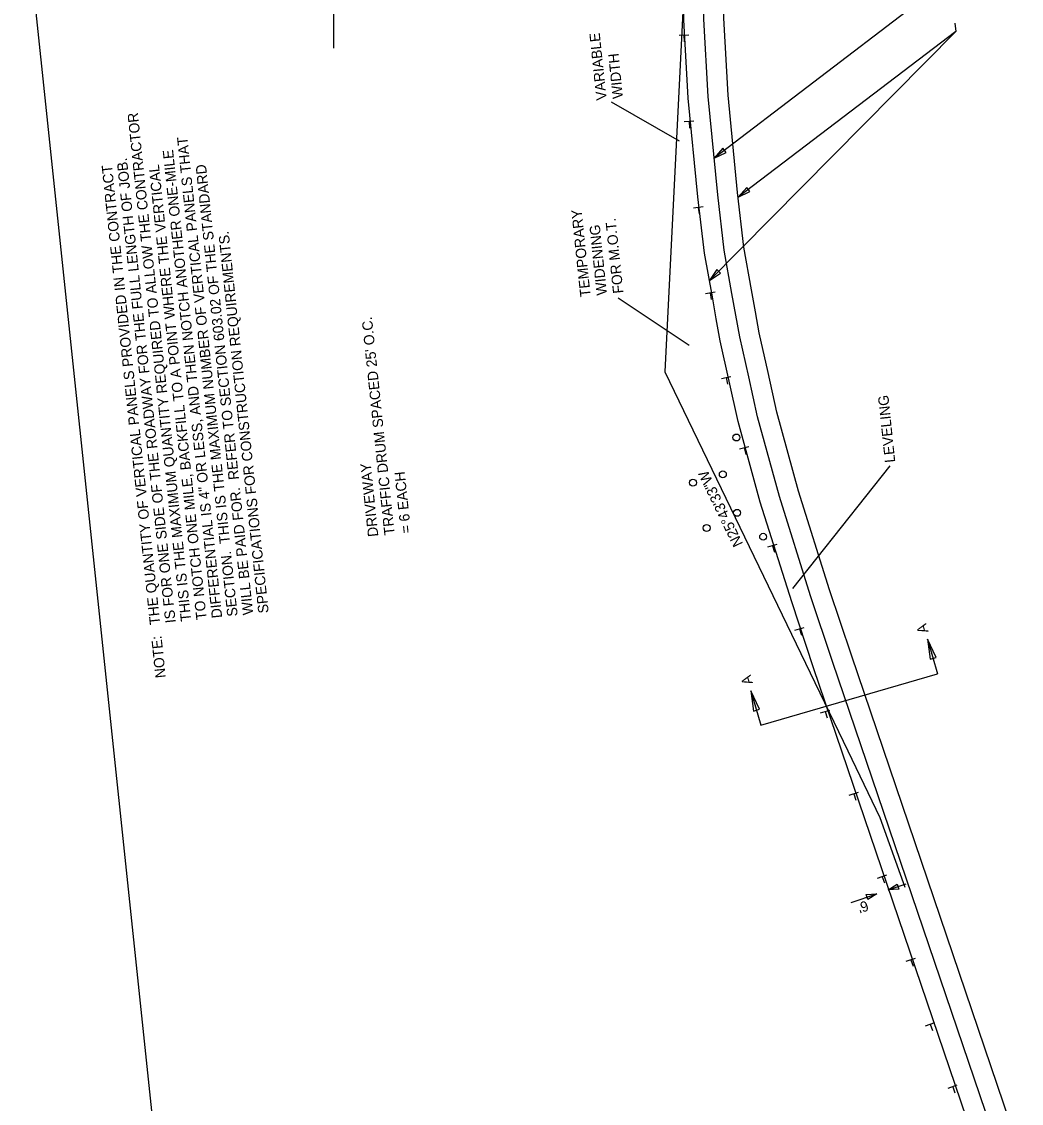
# Model space of a CAD drawing. Extents: x 633427 to 634998, y 288285 to 294065.
# Drawn here: x 633842 to 634420, y 288854 to 289479 of the extents above; entities that cross this region are included whole.
import ezdxf

# ---------------------------------------------------------------- set-up
doc = ezdxf.new("R2010")
doc.units = 0
for name, color, linetype in [('59', 7, 'Continuous'), ('Default', 7, 'Continuous'), ('R_50 Horz Alg Ticks', 7, 'Continuous'), ('R_Exist Surface', 7, 'Continuous'), ('R_Vert Alg Annot', 7, 'Continuous'), ('S_BASELINE', 7, 'Continuous'), ('S_GATE', 7, 'Continuous'), ('S_GUARDRAIL', 7, 'Continuous'), ('S_PRIMARY_CTL', 7, 'Continuous'), ('S_SECONDARY_CTL', 7, 'Continuous'), ('S_WATER_UTILITIES', 7, 'Continuous')]:
    doc.layers.add(name, color=color, linetype=linetype)

msp = doc.modelspace()

# ---------------------------------------------------------------- linework, layer by layer
at = {"layer": '59'}
for p, q in [((634221.97, 289471.22), (634227.59, 289471.46)), ((634224.77, 289471.26), (634224.94, 289467.42)), ((634224.92, 289421.3), (634230.53, 289421.68)), ((634227.72, 289421.41), (634227.97, 289417.57)), ((634230.29, 289371.5), (634235.88, 289372.13)), ((634233.08, 289371.73), (634233.51, 289367.92)), ((634237.22, 289321.97), (634242.77, 289322.85)), ((634240, 289322.33), (634240.59, 289318.53)), ((634246.43, 289272.93), (634251.94, 289274.09)), ((634249.19, 289273.43), (634249.98, 289269.67)), ((634256.89, 289232.14), (634262.34, 289233.54)), ((634259.62, 289232.76), (634260.57, 289229.04)), ((634273.27, 289175.53), (634278.66, 289177.15)), ((634275.97, 289176.26), (634277.08, 289172.58)), ((634288.91, 289127.43), (634294.29, 289129.05)), ((634291.61, 289128.16), (634292.72, 289124.48)), ((634303.68, 289079.68), (634309.07, 289081.3)), ((634306.39, 289080.41), (634307.5, 289076.73)), ((634320.18, 289032.17), (634325.57, 289033.8)), ((634322.88, 289032.9), (634323.99, 289029.23)), ((634336.62, 288984.22), (634341.94, 288986.04)), ((634339.29, 288985.05), (634340.53, 288981.42)), ((634353.16, 288936.15), (634358.49, 288937.96)), ((634355.84, 288936.97), (634357.08, 288933.34)), ((634364.36, 288898.95), (634369.68, 288900.77)), ((634367.04, 288899.78), (634368.28, 288896.15)), ((634377.31, 288862.89), (634382.63, 288864.71)), ((634379.98, 288863.72), (634381.23, 288860.09))]:
    msp.add_line(p, q, dxfattribs=at)
for centre in [(634255.06, 289238.77), (634247.24, 289217.54), (634229.99, 289212.67), (634255.49, 289195.24), (634237.89, 289186.49), (634270.52, 289181.41)]:
    msp.add_circle(centre, 2, dxfattribs=at)
at = {"layer": 'Default'}
for p, q in [((634222.21, 289410.01), (634183.02, 289432.47)), ((634227.9, 289291.99), (634186.74, 289319.19)), ((634287.74, 289151.5), (634343.85, 289222.36)), ((634365.44, 289122.3), (634371.26, 289102.25)), ((634269.16, 289072.62), (634371.26, 289102.25)), ((634263.43, 289092.37), (634269.16, 289072.62)), ((634342.66, 288977.39), (634353.17, 288980.93)), ((634321.31, 288970.19), (634336.15, 288975.2))]:
    msp.add_line(p, q, dxfattribs=at)
at = {"layer": 'R_50 Horz Alg Ticks'}
for points in [[(634370.36, 289111.67), (634365.44, 289122.3), (634366.99, 289110.69)], [(634268.34, 289081.74), (634263.43, 289092.37), (634264.97, 289080.76)]]:
    msp.add_lwpolyline(points, close=True, dxfattribs=at)
at = {"layer": 'R_Exist Surface'}
for p, q in [((634357.36, 289487.95), (634242.23, 289400.18)), ((634381.75, 289473.37), (634239.52, 289329.46)), ((634381.75, 289473.37), (634256.04, 289377.53)), ((634381.24, 289478.19), (634381.75, 289473.37))]:
    msp.add_line(p, q, dxfattribs=at)
at = {"layer": 'S_BASELINE'}
msp.add_lwpolyline([(634998.31, 288392.03), (633976.91, 288284.67), (633842.35, 289564.97), (633891.2, 289570.11), (633858.46, 289881.59), (634831, 289983.81)], close=True, dxfattribs=at)
at = {"layer": 'S_GUARDRAIL'}
for points in [[(634247.3, 289405.9), (634242.23, 289400.18), (634249.12, 289403.51)], [(634261.11, 289383.26), (634256.04, 289377.53), (634262.92, 289380.87)], [(634243.69, 289335.88), (634239.52, 289329.46), (634245.83, 289333.78)]]:
    msp.add_lwpolyline(points, close=True, dxfattribs=at)
at = {"layer": 'S_PRIMARY_CTL'}
msp.add_line((634022.66, 289463.61), (634022.66, 289488.29), dxfattribs=at)
at = {"layer": 'S_SECONDARY_CTL'}
for points in [[(634348.82, 288977.88), (634342.66, 288977.39), (634347.86, 288980.73)], [(634329.99, 288974.7), (634336.15, 288975.2), (634330.95, 288971.86)]]:
    msp.add_lwpolyline(points, close=True, dxfattribs=at)
at = {"layer": 'S_WATER_UTILITIES'}
for points in [[(634391.43, 288835.54), (634299.68, 289105.67), (634287, 289143.77), (634268.87, 289201.35), (634256.17, 289247.97), (634250.94, 289271.34), (634245.72, 289294.71), (634243.46, 289307.36), (634241.21, 289320), (634236.7, 289345.3), (634232.84, 289377.82), (634227.32, 289434.84), (634224.79, 289480.07), (634223.78, 289525.15), (634224.08, 289570.66), (634225.94, 289632.66), (634227.62, 289680.27), (634230.44, 289750.4), (634232.4, 289798.28), (634234.34, 289845.36), (634235.37, 289868.82), (634237.56, 289923.11)], [(634402.32, 288839.23), (634310.58, 289109.34), (634297.94, 289147.31), (634279.91, 289204.59), (634267.34, 289250.73), (634262.17, 289273.85), (634256.99, 289296.97), (634254.79, 289309.37), (634252.53, 289322.02), (634248.08, 289346.99), (634244.28, 289379.05), (634238.79, 289435.72), (634236.28, 289480.52), (634235.28, 289525.24), (634235.58, 289570.45), (634237.43, 289632.28), (634239.11, 289679.83), (634241.93, 289749.93), (634243.89, 289797.81), (634245.83, 289844.87), (634246.86, 289868.34), (634249.05, 289922.64)], [(634413.21, 288842.93), (634321.48, 289113), (634308.88, 289150.85), (634290.95, 289207.83), (634278.5, 289253.5), (634273.39, 289276.36), (634268.27, 289299.24), (634266.11, 289311.39), (634263.85, 289324.04), (634259.46, 289348.67), (634255.71, 289380.29), (634250.26, 289436.59), (634247.78, 289480.97), (634246.79, 289525.33), (634247.08, 289570.24), (634248.92, 289631.91), (634250.6, 289679.4), (634253.42, 289749.47), (634255.38, 289797.34), (634257.32, 289844.38), (634258.35, 289867.86), (634260.54, 289922.18)], [(634225.87, 289519.66), (634213.8, 289276.8)], [(634213.8, 289276.8), (634319.35, 289057.74)], [(634319.35, 289057.74), (634337.9, 289019.23)], [(634337.9, 289019.23), (634352.34, 288979.01)]]:
    msp.add_lwpolyline(points, dxfattribs=at)

# ---------------------------------------------------------------- texts
at = {"layer": 'Default'}
msp.add_text("6'", height=6, rotation=198.63075, dxfattribs=at).set_placement((634330.15, 288971.38))
at = {"layer": 'R_50 Horz Alg Ticks'}
for s, rotation, p in [('THIS IS THE MAXIMUM QUANTITY REQUIRED TO ALLOW THE CONTRACTOR', 96, (633940.29, 289132.82)), ('SECTION.  THIS IS THE MAXIMUM NUMBER OF VERTICAL PANELS THAT', 96, (633967.14, 289135.64)), ('DIFFERENTIAL IS 4" OR LESS, AND THEN NOTCH ANOTHER ONE-MILE', 96, (633958.19, 289134.7)), ('IS FOR ONE SIDE OF THE ROADWAY FOR THE FULL LENGTH OF JOB.', 96, (633931.34, 289131.88)), ('THE QUANTITY OF VERTICAL PANELS PROVIDED IN THE CONTRACT', 96, (633922.39, 289130.93)), ('TO NOTCH ONE MILE, BACKFILL TO A POINT WHERE THE VERTICAL', 96, (633949.24, 289133.76)), ('WILL BE PAID FOR.  REFER TO SECTION 603.02 OF THE STANDARD', 96, (633976.09, 289136.58)), ('SPECIFICATIONS FOR CONSTRUCTION REQUIREMENTS.', 96, (633985.04, 289137.52)), ('A', 106.18352, (634366.08, 289126.56)), ('NOTE:', 96, (633925.63, 289100.1)), ('A', 106.18352, (634264.74, 289096.82))]:
    msp.add_text(s, height=6, rotation=rotation, dxfattribs=at).set_placement(p)
at = {"layer": 'R_Vert Alg Annot'}
for s, p in [('VARIABLE', (634180.22, 289433.86)), ('WIDTH', (634189.68, 289434.85)), ('TEMPORARY', (634170.96, 289320.28)), ('WIDENING', (634180.42, 289321.27)), ('FOR M.O.T.', (634189.88, 289322.27)), ("TRAFFIC DRUM SPACED 25' O.C.", (634057.82, 289182.7)), ('LEVELING', (634346.86, 289224.55)), ('DRIVEWAY', (634048.36, 289181.71)), ('= 6 EACH', (634067.27, 289183.7))]:
    msp.add_text(s, height=6, rotation=96, dxfattribs=at).set_placement(p)
at = {"layer": 'S_GATE'}
msp.add_text('N25%%d43\'33"W', height=6, rotation=115.82101, dxfattribs=at).set_placement((634259.05, 289177.38))

doc.saveas('drawing.dxf')
